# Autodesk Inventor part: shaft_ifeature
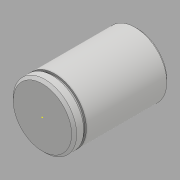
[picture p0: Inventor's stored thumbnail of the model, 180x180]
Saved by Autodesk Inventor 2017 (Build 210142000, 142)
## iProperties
Created: 2016-06
Part Number: shaft_ifeature
Material: Generic
Document SubType Name: Modeling
Designer: CADCIM
Density: 1 g/cm^3
Appearance: Default
Author: CADCIM
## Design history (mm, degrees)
sketch "Sketch1"
  geometry: 1 further point
sketch "Sketch2"
  geometry: L1 (0, 75)-(-25, 75); L2 (-25, 75)-(-25, 9.65); L3 (-25, 9.65)-(-23.5, 9.65); L4 (-23.5, 9.65)-(-23.5, 7.5); L5 (-23.5, 7.5)-(-25, 7.5); L6 (-25, 7.5)-(-25, 0); L7 (-25, 0)-(0, 0); L8 (0, 0)-(0, 75)
  constraints: 16 end point, 6 perpendicular, 2 point on line, 1 horizontal
  dimensions: "d0" = 50 diameter of L6.end L8; "d1" = 47 diameter of L4.end L8; "d2" = 2.15 distance of L3.end L4.end; "d3" = 75 distance of L6.end L1.end; "d4" = 7.5 distance of L5.end L6.end
revolve "Revolution1" sketch "Sketch2" stored, may be unused: angle "d5" = 90 deg
chamfer "Chamfer1" distance "d6" = 2; stored, may be unused: second distance "d7" = 2, angle "d8" = 45 deg
chamfer "Chamfer2" distance "d9" = 2; stored, may be unused: second distance "d10" = 2, angle "d11" = 45 deg
body "Solid1"
